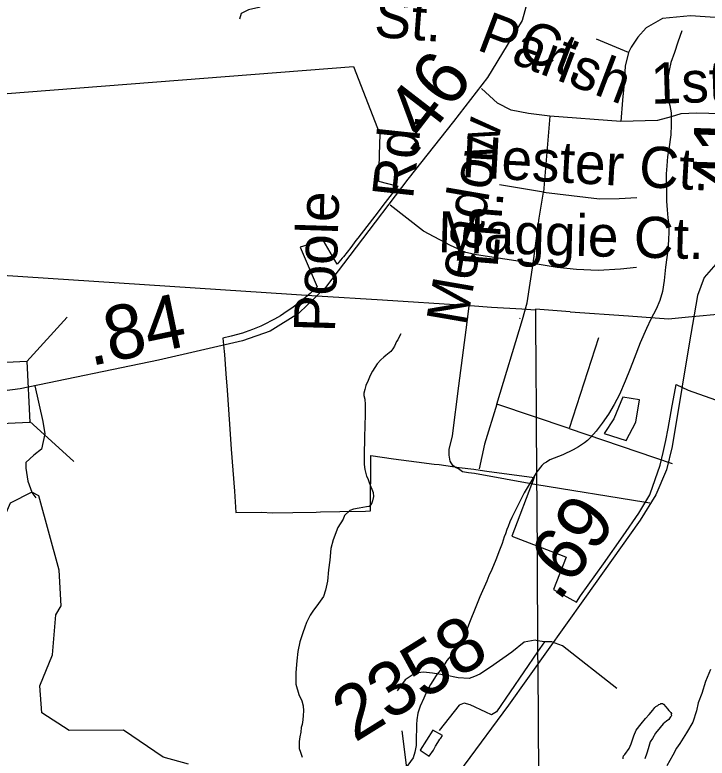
# Model space of a CAD drawing. Extents: x 2001466 to 31450019, y -30647475 to 847247.
# Drawn here: x 2183066 to 2186259, y 736135 to 739564 of the extents above; entities that cross this region are included whole.
import ezdxf

# ---------------------------------------------------------------- set-up
doc = ezdxf.new("R2010")
doc.units = 0
for name, color, linetype in [('Exist Boundary Political City Limit New', 7, 'Continuous'), ('Exist Boundary Political City Limit New Hole', 7, 'Continuous'), ('Exist Hydrographic Creek Single Shore', 7, 'Continuous'), ('Exist Hydrographic Misc Water Feature', 7, 'Continuous'), ('Exist Road Non-System Type 51', 7, 'Continuous'), ('Exist Road Non-System Type 51 Label', 7, 'Continuous'), ('Exist Road Secondary Mileage Hundredths English Label', 7, 'Continuous'), ('Exist Road Secondary Structure Standard Bridge CELL', 7, 'Continuous'), ('Exist Road Secondary Type 51 Attributed', 7, 'Continuous'), ('Exist Road Secondary Type 51 Label', 7, 'Continuous'), ('Exist Road Secondary Type 51 Number Label', 7, 'Continuous'), ('Exist Utilities Electrical Transmission Line', 7, 'Continuous'), ('Map Preparation Boundary City Limit Buffer Line', 7, 'Continuous')]:
    doc.layers.add(name, color=color, linetype=linetype)

msp = doc.modelspace()

# ---------------------------------------------------------------- linework, layer by layer
at = {"layer": 'Exist Boundary Political City Limit New'}
msp.add_lwpolyline([(2182437.2, 739154.6), (2184627.8, 739324.8), (2184749, 739013.9), (2184747.2, 738917.4), (2184743.8, 738796.9), (2184832, 738774.1), (2184773.5, 738697.7), (2184726.5, 738635.5), (2184690, 738587.9), (2184647.8, 738533.3), (2184639.2, 738522.2), (2184615.2, 738490.8), (2184582.2, 738447.8), (2184576.5, 738441.1), (2184552.5, 738413.1), (2184488.2, 738524.2), (2184382.5, 738491.8), (2184461, 738309.9), (2184428.8, 738278.9), (2184388, 738244.1), (2184349.5, 738214.8), (2184306.8, 738185.8), (2184291, 738175.6), (2184263.2, 738159.8), (2184210.5, 738132.9), (2184200.5, 738128.3), (2184162.8, 738112.8), (2184128.2, 738099.9), (2184115.8, 738096.2), (2184064, 738081.4), (2184026, 738072.1), (2184031.5, 738011.4), (2184032.8, 737996.6), (2184039.2, 737907.9), (2184044.8, 737832.5), (2184051.2, 737743.5), (2184057.8, 737652.7), (2184064.5, 737559.9), (2184071.5, 737463.4), (2184078.5, 737366.4), (2184085.8, 737267.8), (2184204.2, 737269.7), (2184254.8, 737267.3), (2184348.5, 737268.1), (2184456.2, 737270.4), (2184476.2, 737270.9), (2184564.8, 737273.2), (2184682.8, 737275.1), (2184707, 737275.6), (2184707, 737389.1), (2184708, 737408.4), (2184707.8, 737487.9), (2184708.2, 737530.6), (2184812, 737516.4), (2184918.2, 737501.8), (2185000, 737491.8), (2185023.8, 737488.9), (2185115.2, 737476.5), (2185183.5, 737467.7), (2185233, 737460.8), (2185243.5, 737459.4), (2185462, 737428.9), (2185358, 737158.5), (2185598.2, 737066.3), (2185609.2, 737062.1), (2185551.2, 736913.1), (2185656, 736854.6), (2185675.5, 736883.6), (2185781.5, 737031.7), (2185871.5, 737159.9), (2185944, 737265.4), (2185995, 737350.3), (2185996.8, 737354.9), (2186043.2, 737486.8), (2186057, 737545.1), (2186069.5, 737600.1), (2186079.5, 737656.4), (2186098.2, 737760.6), (2186108.2, 737816.9), (2186115.8, 737858.9), (2186172.2, 737832.8), (2186349.8, 737770.1)], dxfattribs=at)
at = {"layer": 'Exist Boundary Political City Limit New Hole'}
msp.add_lwpolyline([(2185784.8, 737632.5), (2185885.8, 737600.9), (2185929.8, 737684.6), (2185948, 737787.6), (2185869.8, 737800.8), (2185860.5, 737778.5), (2185828.5, 737700.8), (2185784.8, 737632.5)], dxfattribs=at)
at = {"layer": 'Exist Hydrographic Creek Single Shore'}
for points in [[(2183143.8, 737361.9), (2183043.9, 737311.5), (2182994.9, 737201), (2182929.9, 736867.7), (2182854.9, 736869.2), (2182661.9, 737033.9), (2182775.9, 737533.5), (2182866.9, 737669.9), (2182839.8, 737745.4), (2182829.5, 737807.8), (2182825.1, 737855.4), (2182814.8, 737873.8), (2182665, 738014.7), (2182648, 738165.9), (2182512.9, 738372), (2182511.9, 738392.9)], [(2183866.8, 736107.2), (2183749.9, 736139.1), (2183566.8, 736264.3), (2183316.9, 736262.8), (2183191, 736344), (2183181.9, 736468.9), (2183240, 736612), (2183254.9, 736795.5), (2183280, 736837.5), (2183270.9, 737001.8), (2183177, 737344.9), (2183143.8, 737361.9)]]:
    msp.add_lwpolyline(points, dxfattribs=at)
at = {"layer": 'Exist Hydrographic Misc Water Feature'}
for points in [[(2186142.7, 739490.4), (2186124.6, 739438.3), (2186109.5, 739389.9), (2186091.6, 739343.9), (2186083.8, 739307.8), (2186076.3, 739263.9), (2186074.4, 739220), (2186078.7, 739180), (2186087.1, 739145.9), (2186092.9, 739112.1), (2186093.9, 739056), (2186091.6, 739010.1), (2186082.4, 738944.1), (2186076.7, 738910.2), (2186073.2, 738868.1), (2186071.1, 738829.9), (2186071.1, 738790.1), (2186071.7, 738751.9), (2186072.2, 738703.9), (2186074.4, 738663.8), (2186078.7, 738628), (2186082.6, 738596.1), (2186083.4, 738562.3), (2186081.2, 738526.1), (2186077.5, 738478), (2186067.8, 738400), (2186060.5, 738338.2), (2186053.1, 738287.8), (2186041.4, 738245.8), (2186023.6, 738205.9), (2185999.8, 738159.6), (2185980.1, 738117.5), (2185950.8, 738051.3), (2185923.1, 737979.3), (2185903.6, 737931.1), (2185881.9, 737874.8), (2185854.6, 737812.8), (2185830.6, 737766.5), (2185805, 737722.5), (2185775, 737680.4), (2185747.4, 737644), (2185721.5, 737613.9), (2185708.2, 737600), (2185693.6, 737589.7), (2185665.9, 737571.5), (2185642, 737557.3), (2185594.4, 737534.9), (2185534.3, 737510.7), (2185518.7, 737500.5), (2185506.6, 737494.6), (2185496.4, 737484.4), (2185473, 737456.3)], [(2184846.4, 738092.9), (2184838.6, 738079.1), (2184832.4, 738065), (2184826.7, 738056.9), (2184822.6, 738047), (2184816.8, 738034.9), (2184808.8, 738022.7), (2184800.8, 738010.6), (2184777, 737992.6), (2184768.8, 737984.6), (2184754.9, 737972.5), (2184737.1, 737954.5), (2184727.2, 737936.5), (2184715.3, 737920.5), (2184707.3, 737906.2), (2184701.2, 737892.2), (2184695.6, 737876.4), (2184685.6, 737854.4), (2184679.8, 737836.1), (2184676.2, 737818.1), (2184676.2, 737807.9), (2184680.5, 737790.3), (2184682.3, 737766), (2184682.3, 737722.2), (2184681.1, 737666.4), (2184679.2, 737618), (2184677.4, 737530.3), (2184678, 737490), (2184680.1, 737466.2), (2184688.1, 737436.2), (2184694.2, 737424.3), (2184700.1, 737406.4), (2184708.4, 737386.5), (2184712.7, 737376.5), (2184718.4, 737360.6), (2184720.5, 737342.4), (2184716.3, 737322.4), (2184713.1, 737312.3), (2184708.8, 737302.4), (2184701, 737296.3), (2184688.7, 737294.5), (2184655, 737288.2), (2184628.8, 737284.1), (2184610.7, 737277.9), (2184587.2, 737253.9), (2184581.2, 737237.8), (2184555.2, 737199.5), (2184533.6, 737141.5), (2184524, 737101.6), (2184518.5, 737047.7), (2184512.7, 737003.5), (2184508.8, 736951.3), (2184499.2, 736909.4), (2184489.6, 736881.3), (2184459.6, 736837.1), (2184443.6, 736817.2), (2184428, 736795.2), (2184419.8, 736779), (2184411.6, 736761.2), (2184404.1, 736738.8), (2184394.4, 736713.1), (2184380.5, 736671), (2184370.6, 736627.1), (2184366.9, 736584.6), (2184361.4, 736530.7), (2184361.8, 736476.6), (2184376, 736428.7), (2184390.1, 736399), (2184396.3, 736376.9), (2184398.1, 736353.2), (2184396.7, 736331.1), (2184394.6, 736311.1), (2184390.7, 736291), (2184386.8, 736277), (2184384.8, 736255), (2184380.7, 736232.8), (2184377, 736211.1), (2184377.2, 736191.2), (2184377.2, 736179), (2184383.5, 736163.1), (2184391.3, 736139.2)], [(2185473, 737456.3), (2185415.6, 737358.7), (2185358.8, 737245.2), (2185348.7, 737225.6), (2185341.3, 737203.6), (2185335.2, 737189.9), (2185329.2, 737170.1), (2185323.3, 737156.4), (2185313.7, 737124.6), (2185302, 737094.8), (2185284.1, 737049.2), (2185266.1, 737005.2), (2185252.4, 736975.7), (2185242.7, 736951.6), (2185211.1, 736879.3), (2185191.7, 736833.2), (2185163.6, 736761.2), (2185151.7, 736731.3), (2185134.5, 736690.9), (2185114.2, 736659.1), (2185088.7, 736620.7), (2185058.4, 736584.8), (2185036.6, 736550.7), (2185012.9, 736520.6), (2185009.2, 736516.3), (2184983.1, 736474.4), (2184967.9, 736446.4), (2184952, 736412.2), (2184935.8, 736374.1), (2184924.1, 736342.2), (2184920.4, 736311.9), (2184918.5, 736289.9), (2184918.9, 736261.9), (2184916.5, 736237.9), (2184916.9, 736220), (2184916.9, 736194), (2184911.1, 736162), (2184903.4, 736136), (2184865.8, 736085.7)], [(2186274.7, 736544.2), (2186267.2, 736526.2), (2186251.4, 736488), (2186235.6, 736434), (2186218.2, 736389.7), (2186210.4, 736353.9), (2186192.7, 736301.8), (2186164.8, 736251.7), (2186133.5, 736203.3), (2186117.5, 736181.3), (2186101.5, 736149.3), (2186074, 736099)], [(2185932.7, 736264), (2185954.9, 736293.9), (2185974.5, 736318.1), (2185992.4, 736336.1), (2186008.6, 736356.4), (2186018.2, 736368.3), (2186022.3, 736372.6), (2186028.1, 736376.6), (2186032.2, 736378.4), (2186036.3, 736382.6), (2186042.2, 736384.6), (2186046.3, 736386.8), (2186053.9, 736386.8), (2186058.2, 736384.6), (2186068.3, 736372.5), (2186076.3, 736362.8), (2186082.2, 736355), (2186088.4, 736348.8), (2186092.5, 736345), (2186094.3, 736341), (2186094.1, 736337), (2186094.3, 736330.9), (2186090.4, 736325), (2186086.7, 736321.1), (2186082.4, 736312.8), (2186072.6, 736304.9), (2186056.6, 736292.8), (2186042.8, 736276.6), (2186021.1, 736250.7), (2186007.4, 736226.4), (2185997.3, 736210.4), (2185987.9, 736178.2), (2185981.9, 736158.4), (2185972.1, 736132.3)], [(2185038.7, 736238.9), (2184994.6, 736264.6), (2184934.9, 736172.2), (2184977.4, 736144.3), (2184997.1, 736172.6), (2185006.9, 736190.5), (2185016.8, 736206.5), (2185026.6, 736222.5), (2185030.7, 736226.7), (2185038.7, 736238.9)], [(2185871.6, 736131.7), (2185871.8, 736137.3), (2185873.9, 736145.5), (2185879.6, 736151.6), (2185899.7, 736179.8), (2185909.3, 736201.8), (2185921.2, 736237.8), (2185932.7, 736264)]]:
    msp.add_lwpolyline(points, dxfattribs=at)
at = {"layer": 'Exist Road Non-System Type 51'}
for p, q in [((2186532.5, 739534.7), (2186182.8, 739560)), ((2185896.7, 739390.1), (2185749.7, 739451)), ((2185533.9, 739097.1), (2185505.2, 738745.7)), ((2185861.3, 739072), (2185533.9, 739097.1)), ((2185505.2, 738745.7), (2185302.1, 738779.2)), ((2185484.5, 738625.6), (2185505.2, 738745.7)), ((2185456.3, 738416.2), (2185484.5, 738625.6)), ((2185152.7, 738146.4), (2185162.4, 738221)), ((2185395.3, 738163.6), (2185395.6, 738164.9)), ((2185395.3, 738163.6), (2185397.5, 738164.1)), ((2185114.5, 737852.5), (2185152.7, 738146.4)), ((2185994.4, 737311.4), (2185966.7, 737315.8)), ((2185509, 736671.9), (2185477.3, 736676.9)), ((2185509, 736671.9), (2185477.6, 736626.2))]:
    msp.add_line(p, q, dxfattribs=at)
for points in [[(2184315.9, 739979.8), (2184286.5, 739952.1), (2184269.8, 739877.9), (2184257.9, 739677.1), (2184248.3, 739636.5), (2184224.4, 739612.6), (2184190.9, 739598.2), (2184143.2, 739586.3), (2184109.7, 739569.6), (2184102.5, 739543.3)], [(2186182.8, 739560), (2186053.8, 739547.3), (2185977.8, 739504.2), (2185939.7, 739461.1), (2185909.3, 739415.5), (2185896.7, 739390.1)], [(2185896.7, 739390.1), (2185881.5, 739326.7), (2185876.4, 739248.1), (2185868.8, 739169.5), (2185861.3, 739072)], [(2185533.9, 739097.1), (2185435.9, 739109.1), (2185354.7, 739123.4), (2185292.5, 739156.9), (2185218.5, 739223.8)], [(2186489.7, 739103.1), (2186212.5, 739110.3), (2186138.5, 739107.9), (2186093.1, 739093.5), (2186030.9, 739076.8), (2185861.3, 739072)], [(2185505.2, 738745.7), (2185763.3, 738714.6), (2185854.1, 738717), (2185935.3, 738721.8)], [(2185456.3, 738416.2), (2185195.1, 738456.4), (2185145.7, 738467.4), (2185076.3, 738500.3), (2184950.8, 738566.4), (2184797.9, 738685.9)], [(2185289.9, 737767.9), (2185406.9, 738158.3), (2185428.9, 738235.1), (2185456.3, 738416.2)], [(2185933.4, 738397.9), (2185860.2, 738390.6), (2185756.1, 738385.1), (2185657.3, 738388.7), (2185567.8, 738397.9), (2185456.3, 738416.2)], [(2185757.9, 738073.4), (2185622.6, 737656.4)], [(2183157.6, 737852.1), (2183195.7, 737688.5), (2183204.7, 737630.8), (2183188.5, 737560.4), (2183153.9, 737532.5), (2183116.5, 737499.2), (2183116.5, 737472.1), (2183125.2, 737412.9), (2183143.8, 737361.9)], [(2185472.8, 737395.3), (2185186.2, 737448.1), (2185158.1, 737451.8), (2185130.2, 737455.6), (2185112.1, 737469.4), (2185098, 737475.3), (2185085.8, 737485.1), (2185073.6, 737505), (2185069.4, 737532.8), (2185068.9, 737558.8), (2185084.4, 737621.1), (2185114.5, 737852.5)], [(2185289.9, 737767.9), (2185232.9, 737582.8), (2185207.3, 737469.4)], [(2185622.6, 737656.4), (2185289.9, 737767.9)], [(2185622.6, 737656.4), (2186097.9, 737493.6)], [(2185966.7, 737315.8), (2185473.5, 737395.2), (2185472.8, 737395.3)], [(2183143.8, 737361.9), (2183144.3, 737360.3), (2183163.4, 737336.4)], [(2185477.3, 736676.9), (2185465.5, 736678.8), (2185415.2, 736669.6), (2185358, 736623.8), (2185259.6, 736555.2), (2185211.5, 736523.1), (2185186.4, 736511.7), (2185161.2, 736502.5), (2185110.9, 736504.8), (2185051.4, 736518.5), (2184991.9, 736527.7), (2184950.7, 736532.3), (2184911.8, 736527.7), (2184866, 736495.6), (2184829.4, 736445.3)], [(2185558.9, 736666), (2185543.3, 736671.9), (2185509, 736671.9)], [(2185843.1, 736456.7), (2185591.4, 736653.6), (2185558.9, 736666)], [(2185477.6, 736626.2), (2185287.1, 736349.1), (2185264.2, 736335.4), (2185239, 736346.9), (2185165.8, 736381.2), (2185138.3, 736388.1), (2185115.4, 736378.9), (2185023.9, 736262.2)]]:
    msp.add_lwpolyline(points, dxfattribs=at)
at = {"layer": 'Exist Road Secondary Structure Standard Bridge CELL'}
for p, q in [((2183121.2, 737964.8), (2183306.8, 738169.1)), ((2183134.3, 737689.2), (2183338.5, 737503.5)), ((2184887.7, 735986.6), (2184852.8, 736260.4))]:
    msp.add_line(p, q, dxfattribs=at)
msp.add_lwpolyline([(2182517.4, 737937.4), (2183121.1, 737966.2), (2183134.6, 737684.1), (2182530.8, 737655.3)], close=True, dxfattribs=at)
at = {"layer": 'Exist Road Secondary Type 51 Attributed'}
for points in [[(2185499.9, 739910.6), (2185462.8, 739745.2), (2185406.3, 739537.8), (2185246.2, 739275), (2185089.7, 739071.9), (2184878.4, 738805.9), (2184640.8, 738491.8), (2184498.5, 738305.4), (2184375.1, 738186), (2184244.3, 738104.3), (2184116.6, 738060.3), (2183729.4, 737970.3), (2183091.1, 737838.4), (2182910.1, 737815.3), (2182829.5, 737807.8)], [(2186539.5, 739814.3), (2186538.5, 739555.6), (2186531.1, 739235.2), (2186517.5, 738902.2), (2186510.7, 738457.2), (2186437.5, 738455.1), (2186359, 738442.5), (2186299.4, 738414.3), (2186246, 738352.5), (2186215.6, 738269.8), (2186176.4, 738046.7), (2186141.9, 737842.5), (2186097.4, 737573.4), (2186071.2, 737465.6), (2186023.1, 737349.3), (2185950.4, 737232.1), (2185694, 736870.8), (2185343.5, 736378.7), (2185138.9, 736102.2), (2184858.5, 735711.6), (2184817.9, 735662.7)]]:
    msp.add_lwpolyline(points, dxfattribs=at)
at = {"layer": 'Exist Utilities Electrical Transmission Line'}
for p, q in [((2184459.2, 738266.8), (2182511.9, 738392.9)), ((2184761.8, 738247.2), (2184459.2, 738266.8)), ((2185141.6, 738222.6), (2184761.8, 738247.2)), ((2185162.4, 738221), (2185141.6, 738222.6)), ((2185165.6, 738221), (2185162.4, 738221)), ((2185264.6, 738214.6), (2185165.6, 738221)), ((2186172.9, 738170.1), (2186846.5, 738233.8)), ((2185404.2, 738205.6), (2185264.6, 738214.6)), ((2185467.7, 738201.4), (2185404.2, 738205.6)), ((2185467.7, 738201.4), (2185467.8, 738180.8)), ((2185627.2, 738194.5), (2185896.6, 738174.9)), ((2185467.8, 738180.8), (2185468.1, 738137.4)), ((2185468.1, 738137.4), (2185469.3, 737944.4)), ((2185469.3, 737944.4), (2185470.6, 737738.9)), ((2185470.6, 737738.9), (2185472.8, 737395.3)), ((2185472.8, 737395.3), (2185473.1, 737342.4)), ((2185473.1, 737342.4), (2185477.3, 736676.9)), ((2185477.3, 736676.9), (2185477.6, 736626.2)), ((2185477.6, 736626.2), (2185478, 736553.8)), ((2185478, 736553.8), (2185482.8, 735795.9))]:
    msp.add_line(p, q, dxfattribs=at)
for points in [[(2185627.2, 738194.5), (2185467.7, 738206), (2185467.7, 738201.4)], [(2185896.6, 738174.9), (2186081.8, 738161.5), (2186172.9, 738170.1)]]:
    msp.add_lwpolyline(points, dxfattribs=at)
at = {"layer": 'Map Preparation Boundary City Limit Buffer Line'}
for points in [[(2182437.2, 739154.6), (2184627.8, 739324.8), (2184749, 739013.9), (2184747.2, 738917.4), (2184743.8, 738796.9), (2184832, 738774.1), (2184773.5, 738697.7), (2184726.5, 738635.5), (2184690, 738587.9), (2184647.8, 738533.3), (2184639.2, 738522.2), (2184615.2, 738490.8), (2184582.2, 738447.8), (2184576.5, 738441.1), (2184552.5, 738413.1), (2184488.2, 738524.2), (2184382.5, 738491.8), (2184461, 738309.9), (2184428.8, 738278.9), (2184388, 738244.1), (2184349.5, 738214.8), (2184306.8, 738185.8), (2184291, 738175.6), (2184263.2, 738159.8), (2184210.5, 738132.9), (2184200.5, 738128.3), (2184162.8, 738112.8), (2184128.2, 738099.9), (2184115.8, 738096.2), (2184064, 738081.4), (2184026, 738072.1), (2184031.5, 738011.4), (2184032.8, 737996.6), (2184039.2, 737907.9), (2184044.8, 737832.5), (2184051.2, 737743.5), (2184057.8, 737652.7), (2184064.5, 737559.9), (2184071.5, 737463.4), (2184078.5, 737366.4), (2184085.8, 737267.8), (2184204.2, 737269.7), (2184254.8, 737267.3), (2184348.5, 737268.1), (2184456.2, 737270.4), (2184476.2, 737270.9), (2184564.8, 737273.2), (2184682.8, 737275.1), (2184707, 737275.6), (2184707, 737389.1), (2184708, 737408.4), (2184707.8, 737487.9), (2184708.2, 737530.6), (2184812, 737516.4), (2184918.2, 737501.8), (2185000, 737491.8), (2185023.8, 737488.9), (2185115.2, 737476.5), (2185183.5, 737467.7), (2185233, 737460.8), (2185243.5, 737459.4), (2185462, 737428.9), (2185358, 737158.5), (2185598.2, 737066.3), (2185609.2, 737062.1), (2185551.2, 736913.1), (2185656, 736854.6), (2185675.5, 736883.6), (2185781.5, 737031.7), (2185871.5, 737159.9), (2185944, 737265.4), (2185995, 737350.3), (2185996.8, 737354.9), (2186043.2, 737486.8), (2186057, 737545.1), (2186069.5, 737600.1), (2186079.5, 737656.4), (2186098.2, 737760.6), (2186108.2, 737816.9), (2186115.8, 737858.9), (2186172.2, 737832.8), (2186349.8, 737770.1)], [(2185784.8, 737632.5), (2185885.8, 737600.9), (2185929.8, 737684.6), (2185948, 737787.6), (2185869.8, 737800.8), (2185860.5, 737778.5), (2185828.5, 737700.8), (2185784.8, 737632.5)]]:
    msp.add_lwpolyline(points, dxfattribs=at)

# ---------------------------------------------------------------- texts
at = {"layer": 'Exist Road Non-System Type 51 Label'}
for s, rotation, p in [('St.', 355.6153, (2184719.8, 739462.8)), ('Parish  ', 339.2197, (2185190.7, 739404.6)), ('Ct.', 339.2197, (2185373.1, 739371)), ('1st', 1.848, (2186001.5, 739152.7)), ('Meadow', 80.2216, (2185150.1, 738124.2)), ('Hester Ct.', 356.8058, (2185123.6, 738816.5)), ('Ln.', 85.3352, (2185292.2, 738394.3)), ('Maggie Ct.', 358.4917, (2185015.2, 738468.7))]:
    msp.add_text(s, height=190, rotation=rotation, dxfattribs=at).set_placement(p)
at = {"layer": 'Exist Road Secondary Mileage Hundredths English Label'}
for s, rotation, p in [('.46', 52.323, (2184901.5, 738900.9)), ('.41', 88.1069, (2186436.5, 738641.6)), ('.84', 11.821, (2183415, 737942.9)), ('.69', 54.2328, (2185575.2, 736851.8))]:
    msp.add_text(s, height=250, rotation=rotation, dxfattribs=at).set_placement(p)
at = {"layer": 'Exist Road Secondary Type 51 Label'}
for s, rotation, p in [('Rd.', 83.8965, (2184902.3, 738710.6)), ('Poole', 88.2388, (2184542.4, 738097.7))]:
    msp.add_text(s, height=190, rotation=rotation, dxfattribs=at).set_placement(p)
at = {"layer": 'Exist Road Secondary Type 51 Number Label'}
msp.add_text('2358', height=250, rotation=31.918, dxfattribs=at).set_placement((2184634.4, 736205.1))

doc.saveas('drawing.dxf')
